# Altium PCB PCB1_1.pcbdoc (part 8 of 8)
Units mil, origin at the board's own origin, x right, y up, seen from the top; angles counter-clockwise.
Board outline 3937.01 x 3346.46 mil, 6 copper layers (Top Layer, Signal-1, SIG, POWER, Signal-4, Bottom Layer), stack 60.565 mil thick; 256 components, 201 nets, 1360 pads, 815 vias.
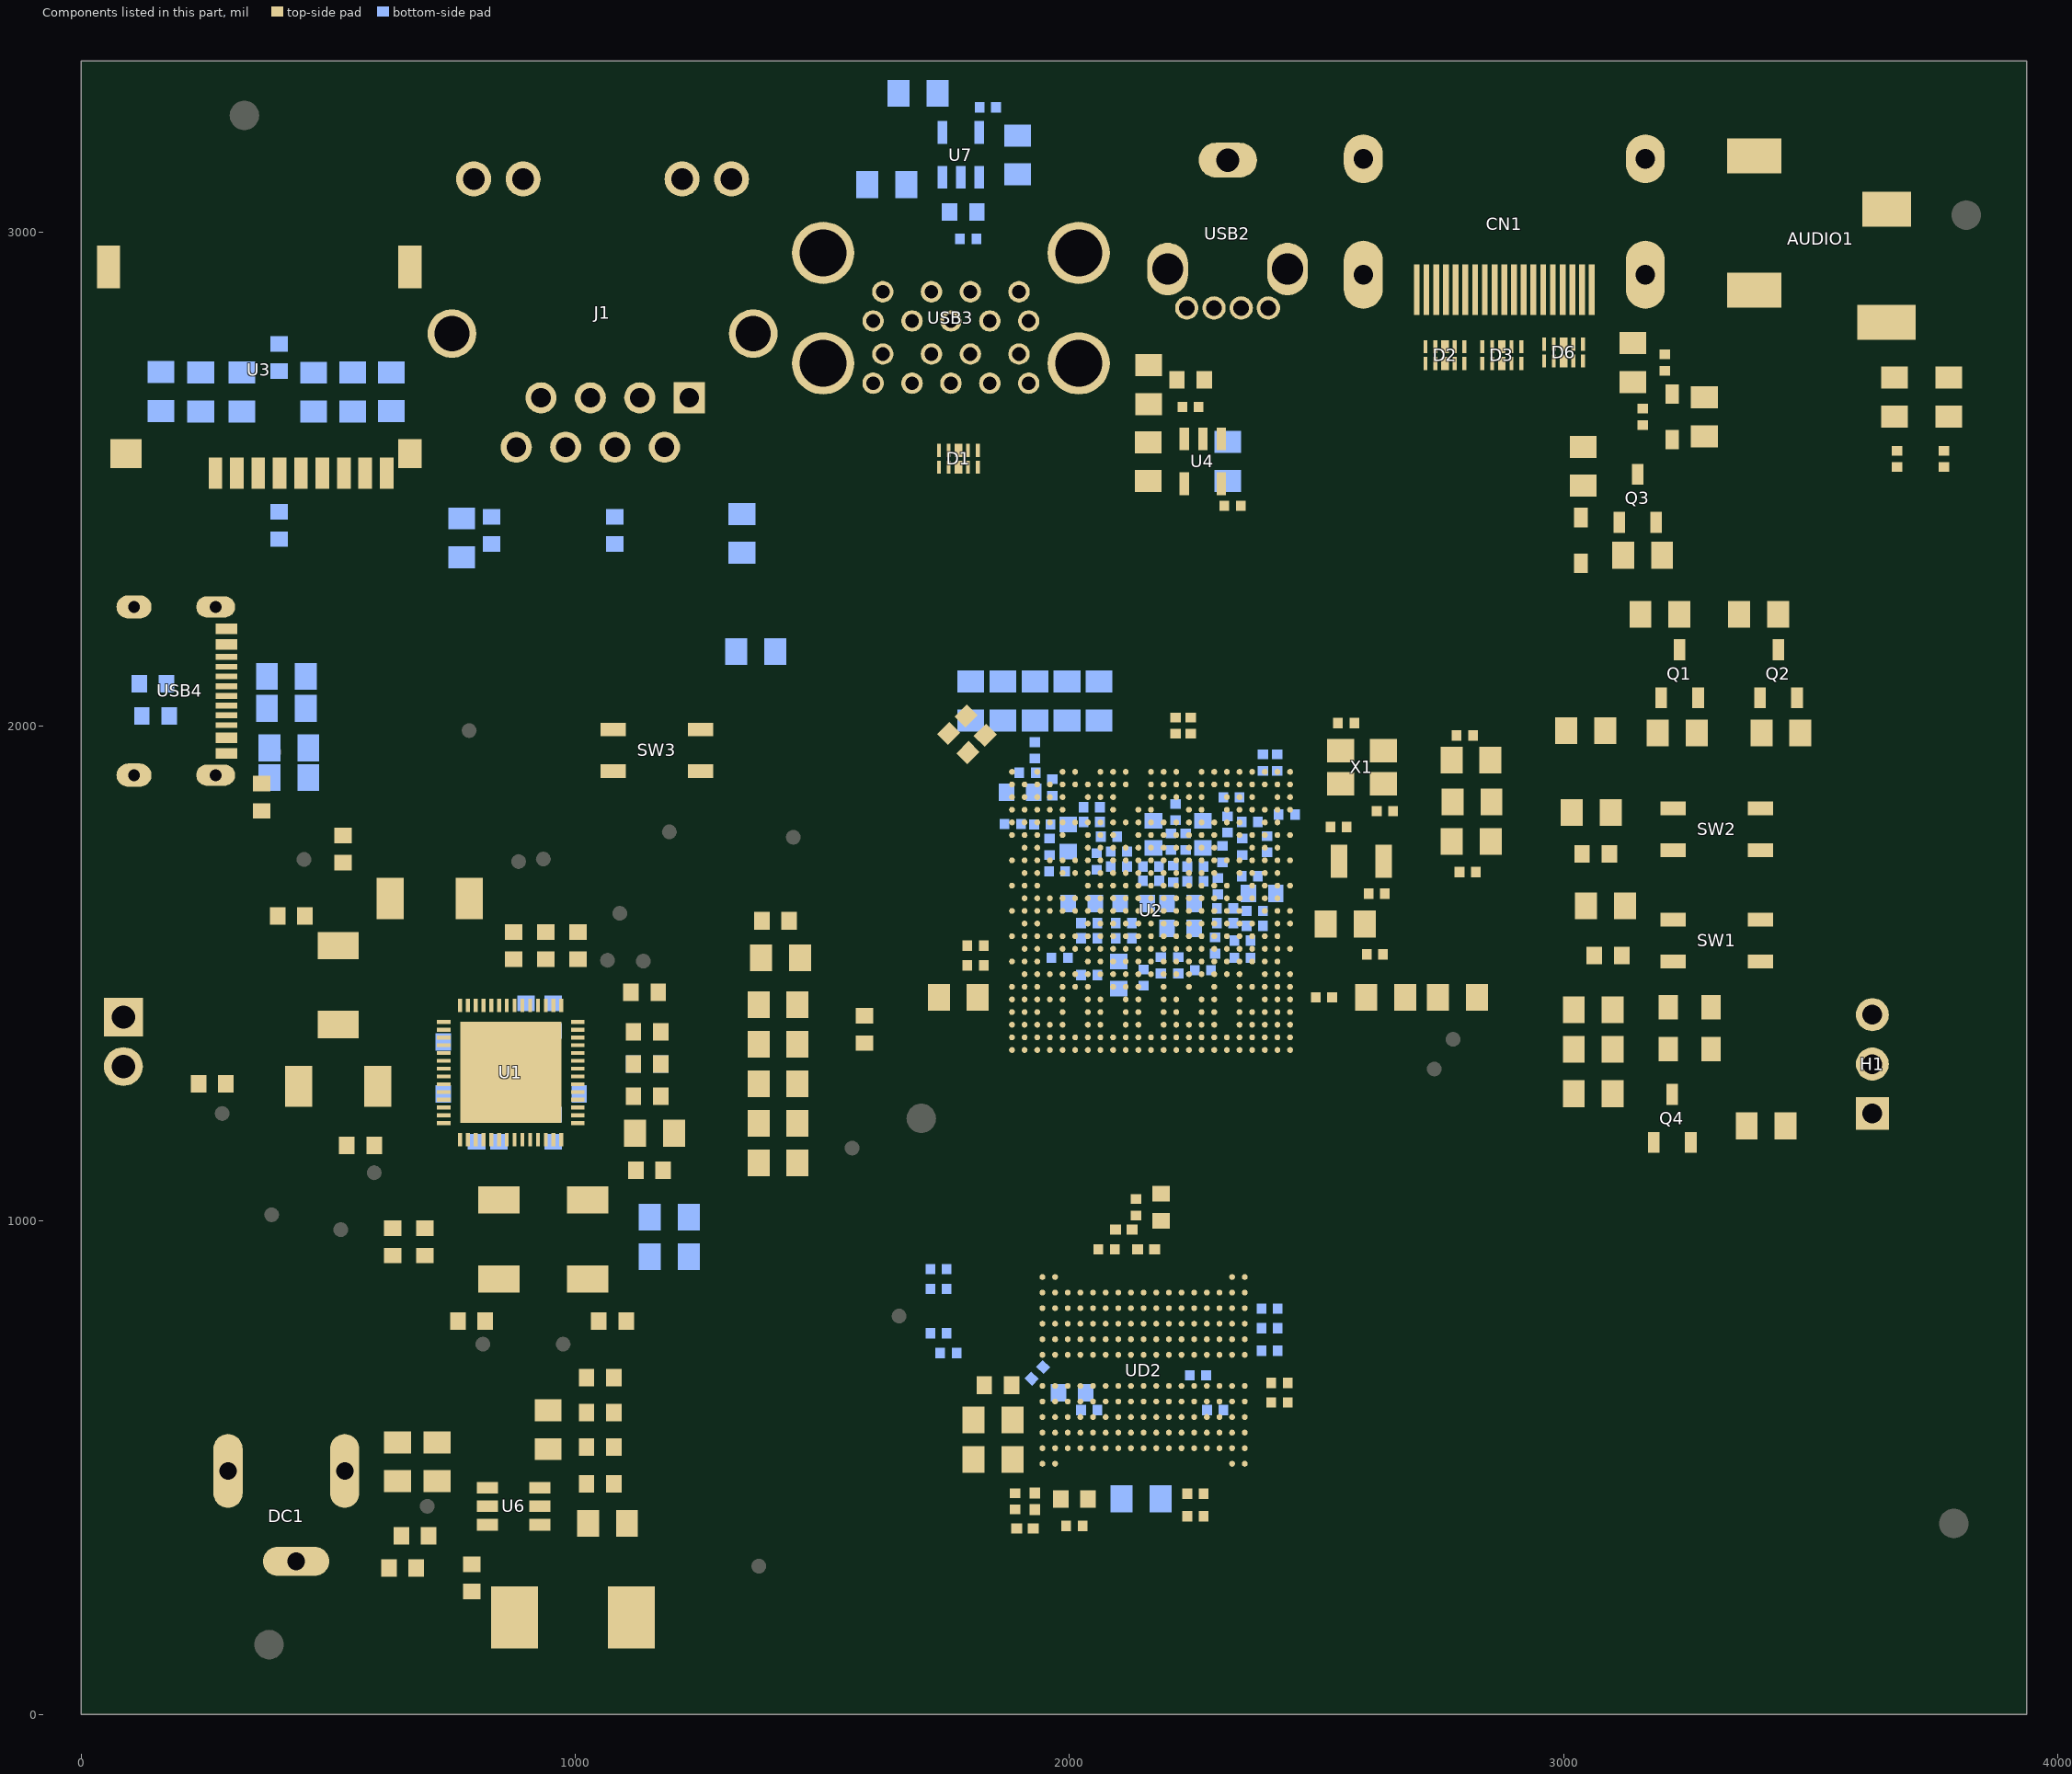
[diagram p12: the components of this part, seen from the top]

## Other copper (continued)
POWER:
  region net AC-LDOIN: 1276.42,3136.72 1287.02,3147.33 1288.46,3146.13 1290.11,3145.15 1291.96,3144.38 1293.95,3143.79 1296.07,3143.36 1298.28,3143.06 1302.82,3142.82 1307.34,3142.88 1311.55,3143.09 1315.21,3143.27 1318.05,3143.28 1280.47,3105.69 1280.47,3108.53 1280.65,3112.19 1280.86,3116.4 1280.93,3120.92 1280.68,3125.47 1280.39,3127.67 1279.95,3129.79 1279.36,3131.79 1278.59,3133.63 1277.61,3135.28
  region net AC-LDOIN: 745.93,3100.41 745.93,3115.41 747.79,3115.58 749.65,3116.06 751.5,3116.82 753.33,3117.81 755.13,3119 756.9,3120.36 760.29,3123.4 763.44,3126.63 766.27,3129.76 768.73,3132.48 770.73,3134.49 770.73,3081.34 768.73,3083.35 766.27,3086.06 763.44,3089.19 760.29,3092.43 756.9,3095.47 755.13,3096.82 753.33,3098.01 751.5,3099.01 749.65,3099.76 747.79,3100.24
  region net AC-LDOIN: 822.98,3147.33 833.58,3136.72 832.39,3135.28 831.41,3133.63 830.64,3131.79 830.05,3129.79 829.61,3127.67 829.32,3125.47 829.07,3120.92 829.14,3116.4 829.35,3112.19 829.53,3108.53 829.53,3105.69 791.95,3143.28 794.79,3143.27 798.45,3143.09 802.66,3142.88 807.18,3142.82 811.72,3143.06 813.93,3143.36 816.05,3143.79 818.04,3144.38 819.89,3145.15 821.54,3146.13
  region net VCC-DRAM: 1907.78,751.54 1907.78,761.54 1909.52,761.62 1911.21,761.85 1912.58,762.17 1913.38,762.54 1913.38,750.54 1912.58,750.91 1911.21,751.23 1909.52,751.45
  region net VCC-DRAM: 1905.11,822.11 1905.11,832.11 1906.85,832.19 1908.53,832.42 1909.91,832.74 1910.71,833.11 1910.71,821.11 1909.91,821.48 1908.53,821.8 1906.85,822.02
  region net BLDO1: 2329.87,1571.7 2322.79,1564.63 2321.5,1565.8 2320.15,1566.83 2318.95,1567.57 2318.13,1567.88 2326.61,1576.37 2326.92,1575.54 2327.66,1574.34 2328.7,1572.99
  region net BLDO2: 2357.34,1866.46 2357.34,1856.46 2355.6,1856.37 2353.92,1856.14 2352.54,1855.82 2351.74,1855.46 2351.74,1867.46 2352.54,1867.09 2353.92,1866.77 2355.6,1866.54
  region net ALDO1: 2364.65,1630.32 2364.65,1620.32 2362.92,1620.23 2361.23,1620 2359.85,1619.68 2359.05,1619.32 2359.05,1631.32 2359.85,1630.95 2361.23,1630.63 2362.92,1630.4
  region net USB-5V: 2294.21,2493.11 2302.45,2513.15 2306.54,2509.31 2308.11,2508.16 2308.68,2507.89 2309.06,2507.89 2303.96,2490.98 2303.35,2491.47 2302.34,2491.7 2299.59,2491.8 2298.07,2491.84 2296.59,2492.01 2295.27,2492.4
  region net USB-5V: 2328.69,2507.09 2328.69,2487.09 2326.54,2487 2324.42,2486.77 2320.42,2486.09 2316.96,2485.4 2314.29,2485.09 2314.29,2509.09 2316.96,2508.77 2320.42,2508.09 2324.42,2507.4 2326.54,2507.17
  region net BLDO1: 2485.46,1473.25 2495.46,1473.25 2495.8,1471.44 2496.71,1469.18 2497.99,1466.85 2499.46,1464.85 2481.46,1464.85 2482.92,1466.85 2484.21,1469.18 2485.11,1471.44
  region net CLDO1: 644.51,2710.27 633.9,2699.66 631.97,2701.42 629.94,2702.97 628.14,2704.08 626.9,2704.54 639.63,2717.27 640.09,2716.03 641.2,2714.23 642.75,2712.2
  region net CLDO1: 3018.66,2323.96 3018.66,2338.96 3021.27,2339.09 3023.8,2339.43 3025.86,2339.91 3027.06,2340.46 3027.06,2322.46 3025.86,2323.01 3023.8,2323.49 3021.27,2323.83
  region net CLDO1: 3051.34,2338.96 3051.34,2323.96 3048.73,2323.83 3046.2,2323.49 3044.14,2323.01 3042.94,2322.46 3042.94,2340.46 3044.14,2339.91 3046.2,2339.43 3048.73,2339.09
  region net CLDO1: 3192.5,1952.12 3177.5,1952.12 3177.37,1954.73 3177.03,1957.26 3176.55,1959.32 3176,1960.52 3194,1960.52 3193.45,1959.32 3192.97,1957.26 3192.63,1954.73
  region net CLDO1: 3177.5,1984.79 3192.5,1984.79 3192.63,1982.19 3192.97,1979.66 3193.45,1977.59 3194,1976.39 3176,1976.39 3176.55,1977.59 3177.03,1979.66 3177.37,1982.19
  region net CLDO1: 2841.34,1453.96 2841.34,1438.96 2838.73,1438.83 2836.2,1438.49 2834.14,1438.01 2832.94,1437.46 2832.94,1455.46 2834.14,1454.91 2836.2,1454.43 2838.73,1454.09
  region net ALDO1: 2469.92,1700.48 2459.92,1700.48 2459.83,1702.22 2459.61,1703.91 2459.29,1705.28 2458.92,1706.08 2470.92,1706.08 2470.55,1705.28 2470.23,1703.91 2470.01,1702.22
  region net ALDO1: 1151.34,2328.96 1151.34,2313.96 1148.73,2313.83 1146.2,2313.49 1144.14,2313.01 1142.94,2312.46 1142.94,2330.46 1144.14,2329.91 1146.2,2329.43 1148.73,2329.09
  region net CLDO2: 1153.75,2297.69 1153.75,2282.69 1151.14,2282.56 1148.61,2282.22 1146.55,2281.74 1145.35,2281.19 1145.35,2299.19 1146.55,2298.64 1148.61,2298.16 1151.14,2297.82
  region net CLDO2: 3132.5,1717.79 3147.5,1717.79 3147.63,1715.19 3147.97,1712.66 3148.45,1710.59 3149,1709.39 3131,1709.39 3131.55,1710.59 3132.03,1712.66 3132.37,1715.19
  region net BLDO2: 2735,1622.79 2745,1622.79 2745.34,1620.99 2746.25,1618.72 2747.53,1616.39 2749,1614.39 2731,1614.39 2732.47,1616.39 2733.75,1618.72 2734.66,1620.99
  region net BLDO2: 2756.34,1613.96 2756.34,1598.96 2753.73,1598.83 2751.2,1598.49 2749.14,1598.01 2747.94,1597.46 2747.94,1615.46 2749.14,1614.91 2751.2,1614.43 2753.73,1614.09
  region net BLDO2: 1182.5,2062.79 1197.5,2062.79 1197.63,2060.19 1197.97,2057.66 1198.45,2055.59 1199,2054.39 1181,2054.39 1181.55,2055.59 1182.03,2057.66 1182.37,2060.19
  region net BLDO1: 2535,1552.79 2545,1552.79 2545.34,1550.99 2546.25,1548.72 2547.53,1546.39 2549,1544.39 2531,1544.39 2532.47,1546.39 2533.75,1548.72 2534.66,1550.99
  region net BLDO1: 2545,1520.12 2535,1520.12 2534.66,1521.93 2533.75,1524.19 2532.47,1526.52 2531,1528.52 2549,1528.52 2547.53,1526.52 2546.25,1524.19 2545.34,1521.93
  region net AC-LDOIN: 1946.34,2093.96 1946.34,2078.96 1943.73,2078.83 1941.2,2078.49 1939.14,2078.01 1937.94,2077.46 1937.94,2095.46 1939.14,2094.91 1941.2,2094.43 1943.73,2094.09
  region net AC-LDOIN: 1913.14,2092.71 1923.75,2103.31 1925.69,2101.56 1927.72,2100.01 1929.51,2098.89 1930.75,2098.43 1918.02,2085.71 1917.56,2086.94 1916.45,2088.74 1914.9,2090.77
  region net AC-LDOIN: 692.5,2024.79 707.5,2024.79 707.63,2022.19 707.97,2019.66 708.45,2017.59 709,2016.39 691,2016.39 691.55,2017.59 692.03,2019.66 692.37,2022.19
  region net AC-LDOIN: 706.25,2025.31 716.86,2014.71 715.1,2012.77 713.55,2010.74 712.44,2008.94 711.98,2007.71 699.25,2020.43 700.49,2020.89 702.28,2022.01 704.32,2023.56
  region net AC-LDOIN: 1978.66,2078.96 1978.66,2093.96 1981.27,2094.09 1983.8,2094.43 1985.86,2094.91 1987.06,2095.46 1987.06,2077.46 1985.86,2078.01 1983.8,2078.49 1981.27,2078.83
  region net AC-LDOIN: 2011.34,2093.96 2011.34,2078.96 2008.73,2078.83 2006.2,2078.49 2004.14,2078.01 2002.94,2077.46 2002.94,2095.46 2004.14,2094.91 2006.2,2094.43 2008.73,2094.09
  region net AC-LDOIN: 2043.66,2078.96 2043.66,2093.96 2046.27,2094.09 2048.8,2094.43 2050.86,2094.91 2052.06,2095.46 2052.06,2077.46 2050.86,2078.01 2048.8,2078.49 2046.27,2078.83
  region net USB-5V: 74,2012.79 86,2012.79 86.26,2010.67 86.94,2008.29 87.9,2006.07 89,2004.39 71,2004.39 72.1,2006.07 73.06,2008.29 73.74,2010.67
  region net USB-5V: 70,2035.86 90,2035.86 90.09,2033.7 90.31,2031.59 91,2027.59 91.69,2024.12 92,2021.46 68,2021.46 68.31,2024.12 69,2027.59 69.69,2031.59 69.91,2033.7
  region net USB-5V: 86,2005.12 74,2005.12 73.74,2007.25 73.06,2009.62 72.1,2011.84 71,2013.52 89,2013.52 87.9,2011.84 86.94,2009.62 86.26,2007.25
  region net USB-5V: 1791.89,3239.2 1777.75,3253.35 1779.21,3254.93 1780.55,3256.59 1782.89,3259.9 1784.85,3262.84 1786.51,3264.94 1803.49,3247.97 1801.38,3246.31 1798.44,3244.34 1795.13,3242 1793.47,3240.67
  region net USB-5V: 1809.4,3266.46 1809.4,3246.46 1807.25,3246.37 1805.13,3246.14 1801.13,3245.46 1797.67,3244.77 1795,3244.46 1795,3268.46 1797.67,3268.14 1801.13,3267.46 1805.13,3266.77 1807.25,3266.54
  region net USB-5V: 3216.89,2564.2 3202.75,2578.35 3204.21,2579.93 3205.55,2581.59 3207.89,2584.9 3209.85,2587.84 3211.51,2589.94 3228.49,2572.97 3226.38,2571.31 3223.44,2569.34 3220.13,2567 3218.47,2565.67
  region net VCC18-RTC: 2446.29,1758.42 2442.76,1754.88 2441.88,1755.33 2440.31,1755.78 2438.36,1756.14 2436.32,1756.37 2444.81,1764.85 2445.03,1762.81 2445.4,1760.86 2445.84,1759.29
  region net VCC18-RTC: 2512.5,1634.79 2517.5,1634.79 2517.65,1634.28 2518.06,1633.55 2519.53,1631.58 2524,1626.39 2506,1626.39 2510.47,1631.58 2511.94,1633.55 2512.35,1634.28
  region net VCC18-RTC: 3067.5,1927.79 3082.5,1927.79 3082.63,1925.19 3082.97,1922.66 3083.45,1920.59 3084,1919.39 3066,1919.39 3066.55,1920.59 3067.03,1922.66 3067.37,1925.19
  region net AP-NMI: 2253.66,2088.96 2253.66,2093.96 2254.18,2094.1 2254.91,2094.52 2256.88,2095.99 2262.06,2100.46 2262.06,2082.46 2256.88,2086.93 2254.91,2088.4 2254.18,2088.81
  region net AP-NMI: 1022.28,1957.28 1025.82,1953.74 1025.56,1953.27 1025.34,1952.47 1024.98,1950.03 1024.48,1943.21 1011.75,1955.93 1018.57,1956.44 1021.01,1956.79 1021.82,1957.02
  region net BIAS-VRAL: 2360.89,1833.96 2360.89,1828.96 2359.95,1828.66 2358.53,1827.86 2356.89,1826.74 2355.29,1825.46 2355.29,1837.46 2356.89,1836.17 2358.53,1835.05 2359.95,1834.26
  region net BIAS-REXT: 2395.93,1838.56 2399.47,1835.02 2399.02,1834.14 2398.57,1832.58 2398.21,1830.62 2397.98,1828.59 2389.5,1837.07 2391.54,1837.29 2393.49,1837.66 2395.06,1838.1
  region net BIAS-REXT: 2709.11,1693.96 2709.11,1698.96 2710.05,1699.26 2711.47,1700.05 2713.11,1701.17 2714.71,1702.46 2714.71,1690.46 2713.11,1691.74 2711.47,1692.86 2710.05,1693.66
  region net BIAS-VRAL: 2706.74,1650.96 2702.24,1655.96 2702.95,1656.05 2703.73,1656.31 2705.33,1657.23 2706.79,1658.54 2707.84,1660.03 2712.34,1648.91 2709.96,1650.08 2708.41,1650.69
  region net VCC-DRAM: 1764.85,893.44 1757.78,886.37 1756.26,887.4 1754.02,888.37 1751.46,889.11 1749.01,889.48 1761.74,902.21 1762.11,899.76 1762.85,897.2 1763.82,894.96
  region net VCC-DRAM: 1765,866.46 1765,856.46 1764.17,856.11 1762.83,855.21 1759.48,852.46 1759.48,870.46 1762.83,867.71 1764.17,866.8
  region net BLDO1: 2471.72,1522.67 2475.93,1517.97 2479.59,1512.83 2482.67,1507.32 2485.12,1501.5 2486.92,1495.45 2493.99,1488.38 2500.85,1491.26 2507.94,1493.52 2515.2,1495.15 2522.57,1496.13 2530,1496.46 2530,1506.46 2523.17,1506.98 2516.42,1508.15 2509.81,1509.95 2503.4,1512.36 2497.25,1515.37 2491.4,1518.95 2485.92,1523.06 2480.86,1527.67 2471.72,1522.67
Signal-4:
  drawing of 93 lines, arcs and shapes, not listed
Bottom Layer:
  drawing of 406 lines, arcs and shapes, not listed

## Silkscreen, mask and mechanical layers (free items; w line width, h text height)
Top Silkscreen Layer:
  drawing of 207 lines, arcs and shapes, not listed
  text "GND" at 305,3156.46 h30
  text "GND" at 3790,2961.46 h30
  text "NC" at 2050,2496.46 h50
  text "开关" at 1045,2056.46 h120
  text "CLDO1" at 860,1931.46 h45 r90
  text "TYPE-C" at 140,1821.46 h45
  text "CPU1" at 615,1816.46 h60 r90
  text "POWER" at 1080,1811.46 h60
  text "AC-ALDIN" at 945,1771.46 h30 r90
  text "CLDO2" at 1210,1771.46 h30
  text "ALDO3" at 895,1766.46 h30 r90
  text "POWER" at 1295,1706.46 h45
  text "CPU-FB" at 1070,1666.46 h30
  text "CPU2" at 260,1651.46 h60
  text "ALDO1" at 1150,1556.46 h30 r90
  text "GPU-FB" at 1075,1546.46 h30 r90
  text "PMU-SDA" at 2795,1381.46 h25
  text "GND" at 3740,1381.46 h45 r90
  text "VCC" at 205,1366.46 h60 r90
  text "RX" at 3740,1291.46 h45 r90
  text "PMU-SCK" at 2684.5,1258.96 h25
  text "TX" at 3740,1186.46 h45 r90
  text "FAN" at 115,1126.46 h60 r90
  text "GND" at 1675,1126.46 h30
  text "GPU" at 210,1116.46 h60
  text "VCC18-RTC" at 1545,1086.46 h30
  text "BLDO2" at 480,1076.46 h45
  text "BLDO1" at 300,926.46 h45
  text "BLDO3" at 445,901.46 h45
  text "VCC-LPDDR3" at 1485,836.46 h30
  text "SYS" at 655,691.46 h60
  text "DRAM" at 835,656.46 h60
  text "GND" at 3765,311.46 h30
  text "RESET" at 1195,216.46 h60
  text "DC" at 395,141.46 h120
  text "GND" at 355,61.46 h30
Bottom Silkscreen Layer:
  drawing of 192 lines, arcs and shapes, not listed
  text "NC" at 1940,3106.46 h45 r180
  text "选择TYPE" at 790,1891.27 h60
  text "选择DC" at 1104.31,946.46 h60
Mechanical Layer:
  circle w0.1: c130,3221.46 r98.43
  circle w0.1: c125,126.46 r98.43
  circle w0.1: c3810,126.46 r98.43
  circle w0.1: c3805,3221.46 r98.43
